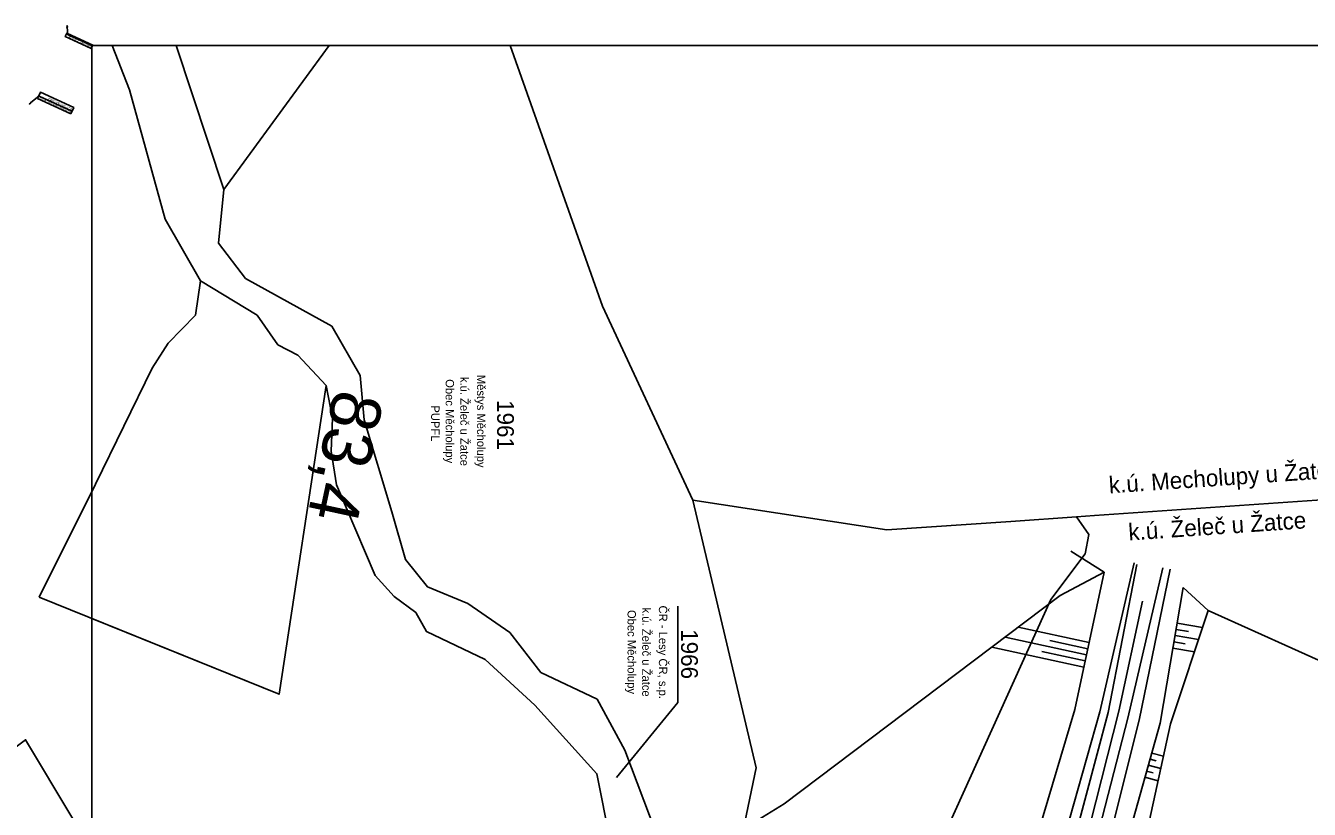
# Model space of a CAD drawing. Extents: x -801372 to -800991, y -1017235 to -1016862.
# Drawn here: x -801225.8 to -801072.7, y -1016996.8 to -1016903.3 of the extents above; entities that cross this region are included whole.
import ezdxf

# ---------------------------------------------------------------- set-up
doc = ezdxf.new("R2010")
doc.units = 0
for name, color, linetype in [('05a - kolej - svršek', 7, 'Continuous'), ('09 - stávající terén', 7, 'Continuous'), ('15 - popisy', 7, 'Continuous'), ('19 - katastr', 7, 'Continuous'), ('19b - katastr - hranice SŽDC', 7, 'Continuous'), ('19b - katastr popisy', 7, 'Continuous'), ('23 - neviditelná', 7, 'Continuous'), ('Hranice parcel', 7, 'Continuous'), ('Vrstva 1 - kolej', 7, 'Continuous'), ('Vrstva 48 - svahy', 7, 'Continuous'), ('Vrstva 55 - k.ú.', 7, 'Continuous'), ('Vrstva 7', 7, 'Continuous')]:
    doc.layers.add(name, color=color, linetype=linetype)

msp = doc.modelspace()

# ---------------------------------------------------------------- linework, layer by layer
at = {"layer": '05a - kolej - svršek'}
for p, q in [((-801093.6, -1016967.42), (-801097.68, -1016985.2)), ((-801093.25, -1016967.64), (-801096.69, -1016985.29)), ((-801090.16, -1016968.04), (-801094.33, -1016985.96)), ((-801089.3, -1016968.16), (-801093, -1016986.19)), ((-801097.68, -1016985.2), (-801101.82, -1016999.87)), ((-801096.69, -1016985.29), (-801100.62, -1017000.08)), ((-801094.33, -1016985.96), (-801098.17, -1017000.77)), ((-801093, -1016986.19), (-801096.75, -1017001.13))]:
    msp.add_line(p, q, dxfattribs=at)
at = {"layer": '09 - stávající terén'}
for p, q in [((-801101.16, -1016966.02), (-801097.15, -1016968.54)), ((-801097.15, -1016968.54), (-801102.41, -1016971.34)), ((-801097.15, -1016968.54), (-801100.68, -1016984.92)), ((-801087.73, -1016970.38), (-801090.5, -1016986.55)), ((-801087.73, -1016970.38), (-801084.74, -1016973.11)), ((-801102.41, -1016971.34), (-801135.36, -1016996.2)), ((-801084.74, -1016973.11), (-801089.25, -1016986.66)), ((-801084.74, -1016973.11), (-801068.6, -1016980.41)), ((-801100.68, -1016984.92), (-801104.98, -1016999.48)), ((-801090.5, -1016986.55), (-801094.66, -1017001.48)), ((-801089.25, -1016986.66), (-801092.62, -1017002.13)), ((-801135.36, -1016996.2), (-801148.04, -1017003.97))]:
    msp.add_line(p, q, dxfattribs=at)
at = {"layer": '15 - popisy'}
for points in [[(-801220.91, -1016903.51), (-801220.9, -1016903.3), (-801220.85, -1016903.5)], [(-801218.01, -1016906.04), (-801221.12, -1016904.61), (-801220.92, -1016904.19), (-801217.82, -1016905.62)], [(-801220.45, -1016913.81), (-801224.41, -1016911.99), (-801224.08, -1016911.26), (-801220.11, -1016913.08)], [(-801225.23, -1016912.55), (-801225.4, -1016912.65), (-801225.27, -1016912.5)]]:
    msp.add_lwpolyline(points, close=True, dxfattribs=at)
for points in [[(-801220.88, -1016903.5), (-801220.79, -1016904.39)], [(-801220.79, -1016904.39), (-801220.7, -1016904.43)], [(-801217.96, -1016905.69), (-801220.7, -1016904.43)], [(-801225.25, -1016912.53), (-801224.24, -1016911.69)], [(-801224.24, -1016911.69), (-801224.15, -1016911.74)], [(-801220.4, -1016913.46), (-801224.15, -1016911.74)]]:
    msp.add_lwpolyline(points, dxfattribs=at)
at = {"layer": '19 - katastr'}
for p, q in [((-801157.02, -1016936.79), (-801168.02, -1016905.67)), ((-801098.33, -1016961.78), (-801100.45, -1016961.93))]:
    msp.add_line(p, q, dxfattribs=at)
for points in [[(-801204.99, -1016933.78), (-801209.21, -1016926.4), (-801213.44, -1016910.95), (-801215.51, -1016905.67)], [(-801202.21, -1016922.85), (-801207.88, -1016905.67)], [(-801189.63, -1016905.67), (-801202.21, -1016922.85)], [(-801202.21, -1016922.85), (-801202.84, -1016929.27), (-801199.62, -1016933.47), (-801189.32, -1016939.19), (-801185.94, -1016945.08), (-801185.46, -1016950.36), (-801182.14, -1016961.34), (-801180.53, -1016967.01), (-801177.89, -1016970.27), (-801173.07, -1016972.28), (-801168.07, -1016975.74), (-801164.36, -1016980.52), (-801157.66, -1016983.69), (-801154.36, -1016989.8), (-801150.62, -1016999.68), (-801150.74, -1017011.59), (-801151.72, -1017024.71), (-801147.17, -1017031.33)], [(-801204.99, -1016933.78), (-801205.59, -1016937.87), (-801208.82, -1016941.19), (-801210.76, -1016944.18), (-801217.52, -1016958.04), (-801224.21, -1016971.53)], [(-801204.99, -1016933.78), (-801205.59, -1016937.87), (-801208.82, -1016941.19), (-801210.76, -1016944.18), (-801217.52, -1016958.04), (-801217.95, -1016958.91)], [(-801190, -1016946.24), (-801193.35, -1016942.64), (-801195.74, -1016941.4), (-801198.22, -1016937.87), (-801204.99, -1016933.78)], [(-801190, -1016946.24), (-801195.61, -1016983.11), (-801224.21, -1016971.53)], [(-801190, -1016946.24), (-801195.61, -1016983.11), (-801217.95, -1016974.06)], [(-801150, -1017036.76), (-801155.85, -1017030.29), (-801158.23, -1017026.66), (-801159.44, -1017022.65), (-801157.64, -1017014.26), (-801156.79, -1017009.49), (-801156.11, -1017000.61), (-801157.69, -1016992.59), (-801165.08, -1016984.43), (-801171.01, -1016978.97), (-801178.02, -1016975.61), (-801179.3, -1016973.37), (-801181.87, -1016971.45), (-801184.14, -1016968.93), (-801188.76, -1016958.13), (-801189.39, -1016954.09), (-801189.23, -1016950.15), (-801190, -1016946.24)], [(-801150, -1017036.76), (-801155.85, -1017030.29), (-801158.23, -1017026.66), (-801159.44, -1017022.65), (-801157.64, -1017014.26), (-801156.79, -1017009.49), (-801156.11, -1017000.61), (-801157.69, -1016992.59), (-801165.08, -1016984.43), (-801171.01, -1016978.97), (-801178.02, -1016975.61), (-801179.3, -1016973.37), (-801181.87, -1016971.45), (-801184.14, -1016968.93), (-801188.76, -1016958.13), (-801189.39, -1016954.09), (-801189.23, -1016950.15), (-801190, -1016946.24)], [(-801146.24, -1016959.95), (-801138.7, -1016991.88), (-801146.17, -1017027.77)], [(-801195.06, -1017041.91), (-801194.93, -1017036.49), (-801202.91, -1017023.23), (-801205.86, -1017018.33), (-801207.37, -1017019.2), (-801214.69, -1017007.21), (-801225.84, -1016988.55), (-801228.75, -1016990.75), (-801232.81, -1016983.18)]]:
    msp.add_lwpolyline(points, dxfattribs=at)
at = {"layer": '19b - katastr - hranice SŽDC'}
msp.add_lwpolyline([(-801146.17, -1017027.77), (-801131.4, -1017034.56), (-801122.73, -1017014.27), (-801103.54, -1016971.8), (-801099.44, -1016966.34), (-801099.01, -1016964.03), (-801100.45, -1016961.93)], dxfattribs=at)
at = {"layer": '19b - katastr popisy'}
for q in [(-801148.04, -1016972.59), (-801155.35, -1016993.04)]:
    msp.add_line((-801148.04, -1016984.11), q, dxfattribs=at)
at = {"layer": '23 - neviditelná'}
msp.add_lwpolyline([(-801217.95, -1016905.67), (-800990.79, -1016905.67), (-800990.79, -1017234.77), (-801217.95, -1017234.77)], close=True, dxfattribs=at)
at = {"layer": 'Hranice parcel'}
msp.add_lwpolyline([(-801190, -1016946.24), (-801193.35, -1016942.64), (-801195.74, -1016941.4), (-801198.22, -1016937.87), (-801204.99, -1016933.78)], dxfattribs=at)
at = {"layer": 'Vrstva 1 - kolej'}
for p, q in [((-801092.58, -1016972), (-801095.4, -1016985.11)), ((-801095.4, -1016985.11), (-801098.85, -1016998.63))]:
    msp.add_line(p, q, dxfattribs=at)
at = {"layer": 'Vrstva 48 - svahy'}
for p, q in [((-801098.96, -1016976.93), (-801107.41, -1016975.11)), ((-801088.59, -1016975.37), (-801087.12, -1016975.62)), ((-801088.46, -1016974.63), (-801085.42, -1016975.15)), ((-801099.27, -1016978.4), (-801108.99, -1016976.31)), ((-801099.11, -1016977.67), (-801103.66, -1016976.69)), ((-801088.84, -1016976.85), (-801087.49, -1016977.08)), ((-801088.71, -1016976.11), (-801085.9, -1016976.59)), ((-801099.59, -1016979.87), (-801110.57, -1016977.5)), ((-801099.43, -1016979.13), (-801104.61, -1016978.02)), ((-801088.97, -1016977.59), (-801086.38, -1016978.03)), ((-801091.69, -1016990.85), (-801090.97, -1016991.05)), ((-801091.49, -1016990.13), (-801090.09, -1016990.52)), ((-801092.1, -1016992.3), (-801091.33, -1016992.51)), ((-801091.9, -1016991.58), (-801090.41, -1016991.99)), ((-801092.3, -1016993.02), (-801090.73, -1016993.46))]:
    msp.add_line(p, q, dxfattribs=at)
at = {"layer": 'Vrstva 55 - k.ú.'}
for points in [[(-801098.33, -1016961.78), (-801100.45, -1016961.93), (-801108.28, -1016962.47), (-801123.1, -1016963.5), (-801146.24, -1016959.95), (-801157.02, -1016936.79), (-801168.02, -1016905.67)], [(-800990.79, -1016936.17), (-801049.4, -1016958.4), (-801065.05, -1016959.48), (-801068.35, -1016959.71), (-801098.33, -1016961.78)]]:
    msp.add_lwpolyline(points, dxfattribs=at)

# ---------------------------------------------------------------- texts
at = {"layer": '15 - popisy'}
for s, p in [('NADZEMNÍ VEDENÍ NN', (-801217.96, -1016905.74)), ('PODZEMNÍ KABELOVÉ VEDENÍ', (-801220.39, -1016913.51)), ('SSZT ÚSTÍ NAD LABEM', (-801220.26, -1016913.2))]:
    msp.add_text(s, height=0.2, rotation=155.3316, dxfattribs=at).set_placement(p)
at = {"layer": '19b - katastr popisy'}
for s, height, p in [('Městys Měcholupy', 1.0001, (-801171.99, -1016944.98)), ('Obec Měcholupy', 1.0001, (-801175.73, -1016945.5)), ('k.ú. Želeč u Žatce ', 1.0001, (-801173.98, -1016945.23)), ('1961', 2, (-801169.59, -1016948)), ('PUPFL', 1, (-801177.46, -1016948.63)), ('ČR - Lesy ČR, s.p.', 1.0001, (-801150.29, -1016972.52)), ('Obec Měcholupy', 1.0001, (-801154.03, -1016973.05)), ('k.ú. Želeč u Žatce ', 1.0001, (-801152.28, -1016972.77)), ('1966', 2, (-801147.64, -1016975.35))]:
    msp.add_text(s, height=height, rotation=270, dxfattribs=at).set_placement(p)
at = {"layer": 'Vrstva 55 - k.ú.'}
for s, p in [('k.ú. Mecholupy u Žatce', (-801096.54, -1016959.14)), ('k.ú. Želeč u Žatce', (-801094.21, -1016964.76))]:
    msp.add_text(s, height=2, rotation=3.9498, dxfattribs=at).set_placement(p)
at = {"layer": 'Vrstva 7'}
msp.add_text('83,4', height=6, rotation=257.8494, dxfattribs=at).set_placement((-801188.95, -1016946.51))

doc.saveas('drawing.dxf')
